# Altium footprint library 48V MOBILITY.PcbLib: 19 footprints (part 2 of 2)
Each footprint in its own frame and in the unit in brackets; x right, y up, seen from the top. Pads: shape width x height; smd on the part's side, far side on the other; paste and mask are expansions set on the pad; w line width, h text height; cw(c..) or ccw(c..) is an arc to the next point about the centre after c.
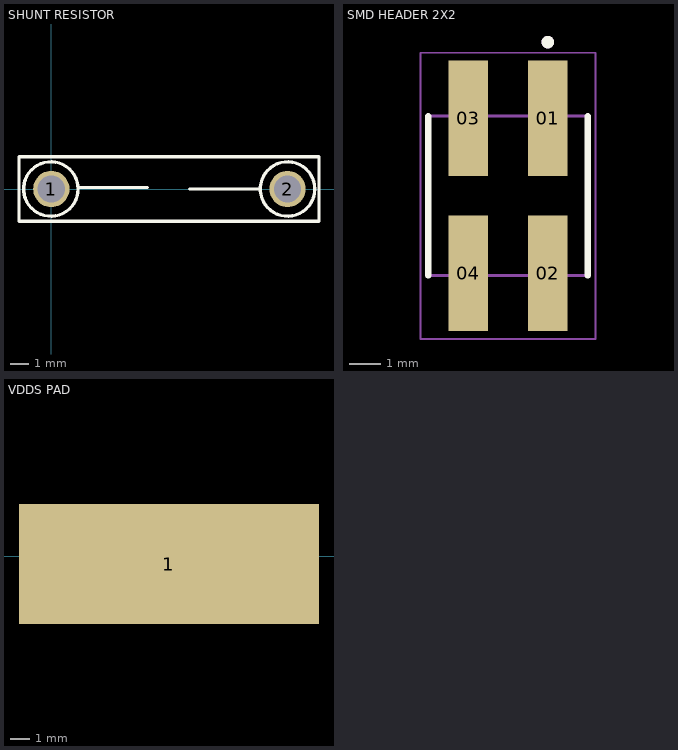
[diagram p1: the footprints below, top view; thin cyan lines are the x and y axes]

## SHUNT RESISTOR [mm] "NA"
height 41
pads (2):
  round 2 hole 1.5: 1(0,0) 2(13,0)
Top Overlay:
  circle w0.178: c-0.025,0 r1.5
  circle w0.178: c13,0 r1.5
  lines w0.178: 1.473,0.076 5.283,0.076 ; 7.62,0 11.43,0 ; -1.778,-1.778 -1.778,1.778 14.732,1.778 14.732,-1.778 -1.778,-1.778
3D body: height 4.57, standoff 3.05, extent -0.762,-0.747 0.754,0.77
3D body: height 4.57, standoff 3.05, extent 12.246,-0.759 13.762,0.759
3D body: height 3.81, standoff -2.54, extent 12.244,-0.76 13.762,0.761
3D body: height 3.81, standoff -2.54, extent -0.762,-0.749 0.756,0.772
3D body: height 4.57, standoff 3.05, extent -0.277,-0.629 12.723,0.889

## SMD HEADER 2X2 [mm]
pads (4):
  rect 1.27x3.68 smd: 01(1269.873,1276.539) 02(1269.873,1271.589) 03(1267.333,1276.539) 04(1267.333,1271.589)
Top Overlay:
  circle w0.2: c1269.873,1278.964 r0.1
  lines w0.2: 1266.063,1271.524 1266.063,1276.604 ; 1271.143,1271.524 1271.143,1276.604
Mechanical 13:
  circle w0.2: c1269.873,1278.964 r0.1
  lines w0.1: 1266.063,1271.524 1266.063,1276.604 1271.143,1276.604 1271.143,1271.524 1266.063,1271.524
Mechanical 15:
  lines w0.05: 1265.813,1269.499 1265.813,1278.629 1271.393,1278.629 1271.393,1269.499 1265.813,1269.499
3D body "step_temp.STEP": height 9.91, standoff 0, extent 1266.063,1270.216 1271.143,1277.912

## VDDS PAD [mm]
pads (1):
  rect 15x6 smd: 1(53.661,-0.378)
